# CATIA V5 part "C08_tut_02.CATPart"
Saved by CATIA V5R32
Part number: Part1
Bounding box of the stored display mesh (mm): x -49.812 to 35, y -44.222 to 44.222, z 0 to 30
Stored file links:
  D:\PROJECTS\Project 2022\CATIA V5 6R 2022\Resources\Tutorial Files\c08_catia_v5_6r2022_tut\C08_tut_02.CATPart
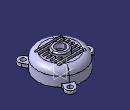
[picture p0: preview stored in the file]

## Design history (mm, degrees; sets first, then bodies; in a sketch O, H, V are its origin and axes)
Body1 (main body)
  Sketch1 on yz-plane, origin (0, 0, 0), H (0, 1, 0), V (0, 0, 1)
    line L1 (0, 0) -> (0, 25)
    line L2 (0, 25) -> (25, 25)
    point P2 (35, 25)
    line L3 (35, 15) -> (35, 0)
    point P3 (35, 0)
    line L4 (35, 0) -> (0, 0)
    reference intersected line E1 through (0, 0) direction (0, 1) from zx-plane
    axis line L5 (0, 41.2428) -> (0, -12.5007)
    point P4 (0, 41.2428)
    arc A1 centre (25, 15) radius 10 from (25, 25) to (35, 15) cw
    radius about axis P3 L5 = 35
    distance P2 P3 = 25
    radius A1 = 10
    horizontal: L2 H, L4 H
    coincidence: P3 H, L1 E1, P4 L1, L2 P2, L3 P2
    vertical: L3 V, L5 V
    tangency: A1 L2, A1 L3
  Shaft1: profile Sketch1, axis Sketch1.L5, angle 360
  Shell1: ExtOffset 0, Face face of Shaft1 from Sketch1.L4, IntOffset 3
  Sketch2 on face of Shaft1 from Sketch1.L4, origin (0, 0, 0), H (1, 0, 0), V (0, -1, 0)
    projected circle E1 centre (0, 0) radius 35 from edge [face of Shaft1 from Sketch1.L3 | face of Shaft1 from Sketch1.L4]
    projected arc E2 centre (0, 0) radius 35 from (-34.187, 7.5) to (-34.187, -7.5) ccw from edge [face of Shaft1 from Sketch1.L3 | face of Shaft1 from Sketch1.L4]
    point P1 (-34.187, 7.5)
    line L1 (-34.187, 7.5) -> (-42.5, 7.5)
    arc A1 centre (-42.5, 0) radius 7.5 from (-42.5, 7.5) to (-42.5, -7.5) ccw
    point P3 (-42.5, 0)
    line L2 (-42.5, -7.5) -> (-34.187, -7.5)
    point P5 (-34.187, -7.5)
    circle A2 centre (-42.5, 0) radius 3.75
    radius A1 = 7.5
    radius A2 = 3.75
    distance P3 V = 42.5
    coincidence: P1 E1, P3 H, P5 E1
    horizontal: L1 H, L2 H
    tangency: A1 L1, L2 A1
  Pad1: profile Sketch2, direction (0, 0, 1), length 5
  CircPattern1: of Pad1, instances 3, angular step 120 {= 360.0*1 deg/CircPattern1.AngularNumber}, axis from face of Shaft1 from Sketch1.L3
  Sketch3 on face of Shaft1 from Sketch1.L2, origin (0, 0, 25), H (1, 0, 0), V (0, 1, 0)
    point P1 (0, -18)
    line L1 (20, -19.75) -> (-20, -19.75)
    line L2 (-20, -16.25) -> (20, -16.25)
    point P5 (-20, -16.25)
    point P6 (20, -18)
    point P7 (-20, -18)
    arc A1 centre (20, -18) radius 1.75 from (20, -19.75) to (20, -16.25) ccw
    arc A2 centre (-20, -18) radius 1.75 from (-20, -16.25) to (-20, -19.75) ccw
    point P8 (-20, -16.25)
    axis line L3 (20, -18) -> (-20, -18)
    distance H P6 = 18
    distance L2 L1 = 3.5
    distance V P6 = 20
    coincidence: P1 V, A2 P5, P5 P8
    horizontal: L1 H, L2 H, L3 H
    equidistance: L1 L2 P1
    tangency: A1 L1, A2 L1, L2 A2, L2 A1
    symmetry: P7 P6 V
  Pocket1: profile Sketch3, direction (0, 0, -1), length 8
  RectPattern1: of Pocket1, direction 1 instances 7, spacing 6, along yz-plane
  Sketch4 on face of Shell1, origin (0, 0, 22), H (1, 0, 0), V (0, -1, 0)
    circle A1 centre (0, 0) radius 12.5
    radius A1 = 12.5
  Pad2: profile Sketch4, direction (0, 0, 1), length 8
  Sketch5 on face of Pad2, origin (0, 0, 22), H (1, 0, 0), V (0, -1, 0)
    circle A1 centre (0, 0) radius 7.5
    radius A1 = 7.5
  Pocket2: profile Sketch5, direction (0, 0, 1), length 8
  Fillet1: radius 2, on edge [end face of Pad2 | face of Pad2 from Sketch4.A1]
